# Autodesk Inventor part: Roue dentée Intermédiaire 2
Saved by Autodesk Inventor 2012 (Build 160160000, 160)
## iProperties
Created: 2013-08
Part Number: Roue dentée Intermédiaire 2
Material: Default
Document SubType Name: Modeling
Designer: hilarion
Density: 1 g/cm^3
Author: Balduini Gael & Faure Olivier
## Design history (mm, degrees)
node "Roue dentée Intermédiaire 21"
node "Roue dentée Intermédiaire 2"
node "Base1"
